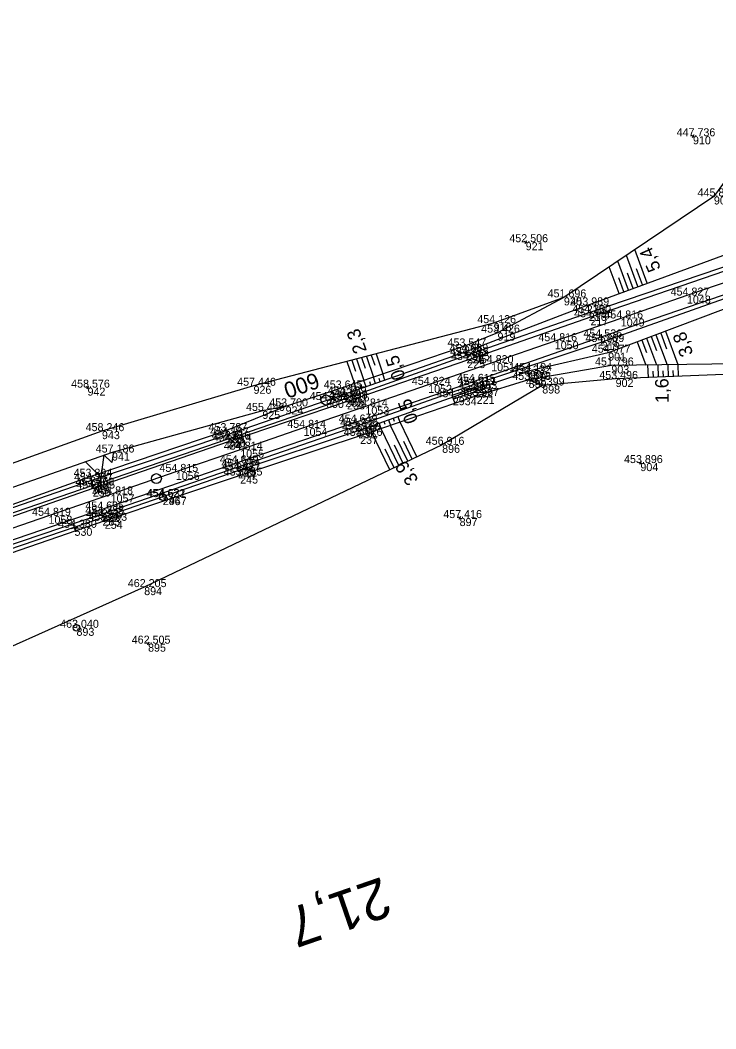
# Model space of a CAD drawing. Extents: x -751615 to -750797, y -1114905 to -1114561.
# Drawn here: x -751316.4 to -751212.2, y -1114822.9 to -1114671.7 of the extents above; entities that cross this region are included whole.
import ezdxf

# ---------------------------------------------------------------- set-up
doc = ezdxf.new("R2010")
doc.units = 0
for name, color, linetype in [('Vrstva 1', 7, 'Continuous'), ('Vrstva 4', 7, 'Continuous'), ('Vrstva 48', 7, 'Continuous'), ('Vrstva 49', 7, 'Continuous'), ('Vrstva 50', 7, 'Continuous'), ('Vrstva 53', 7, 'Continuous'), ('Vrstva 60', 7, 'Continuous'), ('Vrstva 61', 7, 'Continuous'), ('Vrstva 63', 7, 'Continuous'), ('Vrstva 7', 7, 'Continuous'), ('Vrstva 9', 7, 'Continuous')]:
    doc.layers.add(name, color=color, linetype=linetype)

msp = doc.modelspace()

# ---------------------------------------------------------------- linework, layer by layer
at = {"layer": 'Vrstva 1'}
msp.add_lwpolyline([(-751207.29, -1114709.83), (-751216.51, -1114713.01), (-751226.43, -1114716.44), (-751236.32, -1114719.85), (-751245.85, -1114723.14), (-751255.29, -1114726.39), (-751264.7, -1114729.64), (-751273.96, -1114732.84), (-751283.46, -1114736.11), (-751293.11, -1114739.44), (-751302.88, -1114742.81), (-751312.19, -1114746.02), (-751321.76, -1114749.32), (-751331.3, -1114752.61), (-751340.65, -1114755.84), (-751350.4, -1114759.2), (-751359.69, -1114762.41), (-751368.21, -1114765.34), (-751379.18, -1114769.13), (-751388.44, -1114772.32), (-751397.94, -1114775.61), (-751407.38, -1114778.86), (-751416.74, -1114782.09), (-751426.63, -1114785.5)], dxfattribs=at)
at = {"layer": 'Vrstva 4'}
for points in [[(-751187.89, -1114700.58), (-751206.03, -1114707.04), (-751231.23, -1114715.6), (-751249.54, -1114721.97), (-751267.72, -1114728.47), (-751285.3, -1114734.54), (-751305.69, -1114741.51), (-751323.63, -1114747.67), (-751344.16, -1114754.78), (-751362.44, -1114761.12), (-751382.65, -1114768), (-751419.83, -1114780.91), (-751439.84, -1114787.75), (-751459.65, -1114794.56), (-751479.26, -1114801.4), (-751499.56, -1114808.3), (-751517.66, -1114814.61), (-751524.47, -1114817.14), (-751524.91, -1114817.65)], [(-751186.45, -1114705.27), (-751204.57, -1114711.26), (-751229.26, -1114719.97), (-751248.51, -1114726.39), (-751266.03, -1114732.59), (-751283.83, -1114738.73), (-751304.21, -1114745.77), (-751322.37, -1114751.9), (-751342.61, -1114758.9), (-751360.96, -1114765.17), (-751381.11, -1114772.12), (-751418.54, -1114785), (-751438.61, -1114791.91), (-751458.17, -1114798.66), (-751477.81, -1114805.42), (-751497.9, -1114812.48), (-751516.51, -1114818.69), (-751522.39, -1114820.61), (-751523.2, -1114820.52)], [(-751205.8, -1114707.6), (-751230.97, -1114716.26), (-751249.42, -1114722.68), (-751267.45, -1114728.87), (-751285.11, -1114734.87), (-751305.56, -1114741.94), (-751323.35, -1114748.14), (-751343.96, -1114755.23), (-751362.41, -1114761.58), (-751382.45, -1114768.54), (-751419.68, -1114781.41), (-751439.79, -1114788.3), (-751459.37, -1114795.06), (-751479.15, -1114801.88), (-751499.34, -1114808.87), (-751517.57, -1114815.16), (-751524.91, -1114817.65)], [(-751204.68, -1114710.75), (-751229.56, -1114719.28), (-751248.53, -1114725.94), (-751266.25, -1114732.04), (-751284.07, -1114738.15), (-751304.21, -1114745.08), (-751322.47, -1114751.34), (-751342.64, -1114758.27), (-751361.14, -1114764.64), (-751381.34, -1114771.71), (-751418.71, -1114784.62), (-751438.73, -1114791.47), (-751458.26, -1114798.22), (-751477.95, -1114805), (-751498.18, -1114811.91), (-751516.63, -1114818.24), (-751523.2, -1114820.52)]]:
    msp.add_lwpolyline(points, dxfattribs=at)
at = {"layer": 'Vrstva 48'}
for p, q in [((-751222.46, -1114711.15), (-751224.31, -1114706.12)), ((-751225.27, -1114712.18), (-751226.87, -1114707.84)), ((-751223.87, -1114711.67), (-751225.59, -1114706.98)), ((-751226.68, -1114712.7), (-751228.15, -1114708.7)), ((-751223.16, -1114711.41), (-751224.05, -1114708.98)), ((-751225.98, -1114712.44), (-751226.74, -1114710.36)), ((-751224.57, -1114711.93), (-751225.4, -1114709.67)), ((-751219.75, -1114718.35), (-751217.88, -1114723.35)), ((-751223.97, -1114719.94), (-751222.66, -1114723.42)), ((-751223.26, -1114719.67), (-751222.56, -1114721.54)), ((-751222.56, -1114719.41), (-751221.07, -1114723.39)), ((-751221.86, -1114719.15), (-751221.06, -1114721.26)), ((-751221.16, -1114718.88), (-751219.47, -1114723.37)), ((-751220.45, -1114718.62), (-751219.56, -1114720.99)), ((-751267.47, -1114722.87), (-751266.34, -1114726.2)), ((-751266.75, -1114722.68), (-751266.19, -1114724.32)), ((-751266.02, -1114722.49), (-751264.92, -1114725.72)), ((-751265.29, -1114722.31), (-751264.75, -1114723.89)), ((-751264.56, -1114722.12), (-751263.5, -1114725.24)), ((-751263.84, -1114721.93), (-751263.31, -1114723.46)), ((-751263.11, -1114721.74), (-751262.08, -1114724.76)), ((-751222.28, -1114725.31), (-751222.35, -1114723.41)), ((-751221.53, -1114725.28), (-751221.57, -1114724.34)), ((-751220.78, -1114725.25), (-751220.85, -1114723.39)), ((-751220.03, -1114725.22), (-751220.07, -1114724.3)), ((-751219.28, -1114725.19), (-751219.35, -1114723.37)), ((-751218.53, -1114725.16), (-751218.57, -1114724.26)), ((-751217.78, -1114725.13), (-751217.85, -1114723.35)), ((-751264.6, -1114726.67), (-751264.92, -1114725.72)), ((-751263.89, -1114726.42), (-751264.05, -1114725.95)), ((-751263.18, -1114726.18), (-751263.5, -1114725.24)), ((-751262.48, -1114725.93), (-751262.64, -1114725.46)), ((-751261.77, -1114725.68), (-751262.08, -1114724.76)), ((-751266.02, -1114727.16), (-751266.34, -1114726.2)), ((-751265.31, -1114726.92), (-751265.47, -1114726.44)), ((-751262.66, -1114732.13), (-751262.37, -1114732.97)), ((-751261.95, -1114731.88), (-751261.8, -1114732.3)), ((-751261.25, -1114731.63), (-751260.95, -1114732.48)), ((-751260.54, -1114731.38), (-751260.39, -1114731.81)), ((-751259.83, -1114731.13), (-751259.53, -1114731.99)), ((-751257, -1114737.19), (-751259.49, -1114731.98)), ((-751264.08, -1114732.63), (-751263.78, -1114733.45)), ((-751261.06, -1114739.13), (-751263.78, -1114733.45)), ((-751263.37, -1114732.38), (-751263.22, -1114732.79)), ((-751259.71, -1114738.49), (-751262.35, -1114732.96)), ((-751258.36, -1114737.84), (-751260.92, -1114732.47)), ((-751257.68, -1114737.52), (-751258.94, -1114734.87)), ((-751260.39, -1114738.81), (-751261.72, -1114736.01)), ((-751259.03, -1114738.16), (-751260.33, -1114735.44))]:
    msp.add_line(p, q, dxfattribs=at)
at = {"layer": 'Vrstva 49'}
for p, q in [((-751215.38, -1114689.24), (-751215.83, -1114689.02)), ((-751215.5, -1114688.91), (-751215.72, -1114689.36)), ((-751240.46, -1114705.12), (-751240.91, -1114704.9)), ((-751240.57, -1114704.78), (-751240.79, -1114705.23)), ((-751231.53, -1114714.48), (-751209.62, -1114706.44)), ((-751238.2, -1114726.49), (-751240.24, -1114725.65)), ((-751306.12, -1114726.92), (-751306.57, -1114726.7)), ((-751306.24, -1114726.59), (-751306.45, -1114727.04)), ((-751223.27, -1114738.23), (-751223.72, -1114738.01)), ((-751223.38, -1114737.89), (-751223.6, -1114738.34)), ((-751250.35, -1114746.47), (-751250.8, -1114746.25)), ((-751250.47, -1114746.14), (-751250.69, -1114746.58)), ((-751297.04, -1114765.3), (-751297.49, -1114765.08)), ((-751297.16, -1114764.96), (-751297.38, -1114765.41))]:
    msp.add_line(p, q, dxfattribs=at)
for points in [[(-751159.89, -1114710.39), (-751159.56, -1114697.89), (-751162.61, -1114687.69), (-751171.31, -1114676.44), (-751182.9, -1114671.72), (-751191.58, -1114672.91), (-751197.98, -1114678.05), (-751212.47, -1114698.15), (-751234.95, -1114713.28), (-751244.9, -1114718.57)], [(-751201.1, -1114711.81), (-751208.03, -1114713.96), (-751228.32, -1114721.57), (-751240.07, -1114724.3)], [(-751234.95, -1114713.28), (-751245.48, -1114717.14), (-751281.47, -1114726.53), (-751304.18, -1114733.33), (-751349.01, -1114749.46), (-751398.2, -1114766.87), (-751445.8, -1114779.91), (-751491.92, -1114801.09), (-751522.47, -1114813.15), (-751523.88, -1114811.23), (-751530.06, -1114804.52)], [(-751231.53, -1114714.48), (-751249.64, -1114721.46), (-751267.89, -1114727.82), (-751285.51, -1114733.95), (-751305.91, -1114740.8), (-751324, -1114747.03), (-751344.27, -1114754.11), (-751362.59, -1114760.52), (-751382.59, -1114767.44), (-751402.41, -1114774.04), (-751420.23, -1114780.2), (-751439.89, -1114787.15), (-751459.92, -1114794.04), (-751479.47, -1114800.49), (-751499.79, -1114807.5), (-751517.87, -1114814.1), (-751523.11, -1114815.97), (-751524.21, -1114815.64), (-751526.18, -1114811.44)], [(-751244.9, -1114718.57), (-751249.94, -1114720.63), (-751268.48, -1114726.93), (-751276.66, -1114729.62), (-751285.76, -1114733.33), (-751305.98, -1114740.17), (-751324.13, -1114746.66), (-751344.39, -1114753.73), (-751362.68, -1114760.23), (-751382.77, -1114766.9), (-751402.56, -1114773.56), (-751420.5, -1114779.46), (-751440.12, -1114786.64), (-751460.29, -1114793.37), (-751479.7, -1114799.99), (-751499.94, -1114807), (-751518.24, -1114813.43), (-751522.74, -1114814.82), (-751523.67, -1114814.11), (-751524.93, -1114811.32)], [(-751523.9, -1114821.95), (-751516.26, -1114819.37), (-751497.39, -1114813.06), (-751477.62, -1114806.13), (-751458.02, -1114799.12), (-751438.43, -1114792.47), (-751418.48, -1114785.51), (-751400.56, -1114779.53), (-751380.1, -1114772.49), (-751360.67, -1114765.9), (-751342.47, -1114759.51), (-751322.29, -1114752.46), (-751304.11, -1114746.3), (-751283.78, -1114739.21), (-751265.74, -1114733.22), (-751248.29, -1114727.04), (-751240.07, -1114724.3)], [(-751204.75, -1114724.61), (-751227.2, -1114725.51), (-751238.2, -1114726.49), (-751253.2, -1114735.38), (-751297.85, -1114756.71), (-751332.9, -1114772.39), (-751375.5, -1114786.51), (-751400.7, -1114793.56), (-751443.21, -1114803.36), (-751482.54, -1114812.28)], [(-751205.22, -1114723.18), (-751227.84, -1114723.49), (-751240.24, -1114725.65)], [(-751240.24, -1114725.65), (-751248.02, -1114728.05), (-751265.49, -1114734.04), (-751283.47, -1114739.99), (-751303.76, -1114746.77), (-751322.17, -1114753.1), (-751342.49, -1114760), (-751360.52, -1114766.36), (-751379.96, -1114773.04), (-751400.34, -1114780.09), (-751418.29, -1114786.26), (-751438.17, -1114793.17), (-751457.68, -1114799.96), (-751477.22, -1114807.06), (-751497.38, -1114813.97), (-751516.22, -1114820.45), (-751522.92, -1114822.93), (-751523.9, -1114821.95)], [(-751276.66, -1114729.62), (-751280.14, -1114730.3), (-751302.67, -1114736.54), (-751347.76, -1114752.37), (-751397.37, -1114769.54), (-751443.61, -1114786.7), (-751459.32, -1114792.11), (-751460.29, -1114793.37)]]:
    msp.add_lwpolyline(points, dxfattribs=at)
at = {"layer": 'Vrstva 50'}
msp.add_lwpolyline([(-751302.47, -1114736.39), (-751302.69, -1114738.05), (-751303.89, -1114736.88), (-751304.33, -1114740.21), (-751306.72, -1114737.86)], dxfattribs=at)
at = {"layer": 'Vrstva 53'}
msp.add_line((-751307.96, -1114762.79), (-751308.05, -1114762.82), dxfattribs=at)
msp.add_circle((-751308, -1114762.81), 0.499, dxfattribs=at)
at = {"layer": 'Vrstva 60'}
for p, q in [((-751215.61, -1114689.13), (-751215.61, -1114689.13)), ((-751212.47, -1114698.15), (-751212.47, -1114698.15)), ((-751240.68, -1114705.01), (-751240.68, -1114705.01)), ((-751234.95, -1114713.28), (-751234.95, -1114713.28)), ((-751216.51, -1114713.01), (-751216.51, -1114713.01)), ((-751231.53, -1114714.48), (-751231.53, -1114714.48)), ((-751231.23, -1114715.6), (-751231.23, -1114715.6)), ((-751230.97, -1114716.26), (-751230.97, -1114716.26)), ((-751226.43, -1114716.44), (-751226.43, -1114716.44)), ((-751245.48, -1114717.14), (-751245.48, -1114717.14)), ((-751244.9, -1114718.57), (-751244.9, -1114718.57)), ((-751236.32, -1114719.85), (-751236.32, -1114719.85)), ((-751229.56, -1114719.28), (-751229.56, -1114719.28)), ((-751229.26, -1114719.97), (-751229.26, -1114719.97)), ((-751249.94, -1114720.63), (-751249.94, -1114720.63)), ((-751249.64, -1114721.46), (-751249.64, -1114721.46)), ((-751228.32, -1114721.57), (-751228.32, -1114721.57)), ((-751249.54, -1114721.97), (-751249.54, -1114721.97)), ((-751249.42, -1114722.68), (-751249.42, -1114722.68)), ((-751245.85, -1114723.14), (-751245.85, -1114723.14)), ((-751240.07, -1114724.3), (-751240.07, -1114724.3)), ((-751227.84, -1114723.49), (-751227.84, -1114723.49)), ((-751248.53, -1114725.94), (-751248.53, -1114725.94)), ((-751240.28, -1114724.69), (-751240.28, -1114724.69)), ((-751240.24, -1114725.65), (-751240.24, -1114725.65)), ((-751227.2, -1114725.51), (-751227.2, -1114725.51)), ((-751306.34, -1114726.81), (-751306.34, -1114726.81)), ((-751281.47, -1114726.53), (-751281.47, -1114726.53)), ((-751268.48, -1114726.93), (-751268.48, -1114726.93)), ((-751255.29, -1114726.39), (-751255.29, -1114726.39)), ((-751248.51, -1114726.39), (-751248.51, -1114726.39)), ((-751248.29, -1114727.04), (-751248.29, -1114727.04)), ((-751238.2, -1114726.49), (-751238.2, -1114726.49)), ((-751270.6, -1114728.66), (-751270.6, -1114728.66)), ((-751267.89, -1114727.82), (-751267.89, -1114727.82)), ((-751267.72, -1114728.47), (-751267.72, -1114728.47)), ((-751267.45, -1114728.87), (-751267.45, -1114728.87)), ((-751251.6, -1114728.25), (-751251.6, -1114728.25)), ((-751248.02, -1114728.05), (-751248.02, -1114728.05)), ((-751280.14, -1114730.3), (-751280.14, -1114730.3)), ((-751276.66, -1114729.62), (-751276.66, -1114729.62)), ((-751264.7, -1114729.64), (-751264.7, -1114729.64)), ((-751266.25, -1114732.04), (-751266.25, -1114732.04)), ((-751304.18, -1114733.33), (-751304.18, -1114733.33)), ((-751285.76, -1114733.33), (-751285.76, -1114733.33)), ((-751273.96, -1114732.84), (-751273.96, -1114732.84)), ((-751266.03, -1114732.59), (-751266.03, -1114732.59)), ((-751265.74, -1114733.22), (-751265.74, -1114733.22)), ((-751285.51, -1114733.95), (-751285.51, -1114733.95)), ((-751285.3, -1114734.54), (-751285.3, -1114734.54)), ((-751285.11, -1114734.87), (-751285.11, -1114734.87)), ((-751265.49, -1114734.04), (-751265.49, -1114734.04)), ((-751302.67, -1114736.54), (-751302.67, -1114736.54)), ((-751283.46, -1114736.11), (-751283.46, -1114736.11)), ((-751253.2, -1114735.38), (-751253.2, -1114735.38)), ((-751284.07, -1114738.15), (-751284.07, -1114738.15)), ((-751223.49, -1114738.12), (-751223.49, -1114738.12)), ((-751293.11, -1114739.44), (-751293.11, -1114739.44)), ((-751283.83, -1114738.73), (-751283.83, -1114738.73)), ((-751283.78, -1114739.21), (-751283.78, -1114739.21)), ((-751305.98, -1114740.17), (-751305.98, -1114740.17)), ((-751305.91, -1114740.8), (-751305.91, -1114740.8)), ((-751283.47, -1114739.99), (-751283.47, -1114739.99)), ((-751305.69, -1114741.51), (-751305.69, -1114741.51)), ((-751305.56, -1114741.94), (-751305.56, -1114741.94)), ((-751302.88, -1114742.81), (-751302.88, -1114742.81)), ((-751295.08, -1114743.22), (-751295.08, -1114743.22)), ((-751295.05, -1114743.21), (-751295.05, -1114743.21)), ((-751304.21, -1114745.08), (-751304.21, -1114745.08)), ((-751304.21, -1114745.77), (-751304.21, -1114745.77)), ((-751312.19, -1114746.02), (-751312.19, -1114746.02)), ((-751304.11, -1114746.3), (-751304.11, -1114746.3)), ((-751303.76, -1114746.77), (-751303.76, -1114746.77)), ((-751250.58, -1114746.36), (-751250.58, -1114746.36)), ((-751308.3, -1114747.82), (-751308.3, -1114747.82)), ((-751297.85, -1114756.71), (-751297.85, -1114756.71)), ((-751308, -1114762.81), (-751308, -1114762.81)), ((-751297.27, -1114765.19), (-751297.27, -1114765.19))]:
    msp.add_line(p, q, dxfattribs=at)
at = {"layer": 'Vrstva 63'}
msp.add_line((-751270.55, -1114728.64), (-751270.65, -1114728.68), dxfattribs=at)
msp.add_circle((-751270.6, -1114728.66), 0.756, dxfattribs=at)
at = {"layer": 'Vrstva 7'}
for p, q in [((-751239.81, -1114724.52), (-751240.76, -1114724.85)), ((-751240.12, -1114725.16), (-751240.45, -1114724.22)), ((-751295.03, -1114743.21), (-751295.12, -1114743.24)), ((-751295.01, -1114743.19), (-751295.1, -1114743.22)), ((-751307.83, -1114747.65), (-751308.77, -1114747.98)), ((-751308.14, -1114748.29), (-751308.46, -1114747.34))]:
    msp.add_line(p, q, dxfattribs=at)
for centre, radius in [((-751296.03, -1114740.45), 0.75), ((-751295.08, -1114743.22), 0.5), ((-751295.05, -1114743.21), 0.5)]:
    msp.add_circle(centre, radius, dxfattribs=at)
at = {"layer": 'Vrstva 9'}
msp.add_lwpolyline([(-751251.32, -1114729.1), (-751251.51, -1114728.53), (-751251.7, -1114727.96), (-751246.96, -1114726.36), (-751246.77, -1114726.93), (-751251.51, -1114728.53)], dxfattribs=at)

# ---------------------------------------------------------------- texts
at = {"layer": 'Vrstva 48'}
for s, rotation, p in [('5,4', 113.9405, (-751220.38, -1114708.93)), ('2,3', 109.6266, (-751264.45, -1114721.29)), ('3,8', 110.5644, (-751215.54, -1114721.72)), ('0,5', 108.768, (-751258.67, -1114725.29)), ('1,6', 90.77, (-751219.24, -1114729.12)), ('0,5', 109.5075, (-751256.77, -1114731.79)), ('3,9', 123.9304, (-751256.67, -1114740.61))]:
    msp.add_text(s, height=2, rotation=rotation, dxfattribs=at).set_placement(p)
at = {"layer": 'Vrstva 60'}
for s, p in [('910', (-751215.61, -1114690.33)), ('909', (-751212.47, -1114699.35)), ('921', (-751240.68, -1114706.21)), ('920', (-751234.95, -1114714.48)), ('1048', (-751216.51, -1114714.21)), ('215', (-751231.53, -1114715.68)), ('216', (-751231.23, -1114716.8)), ('217', (-751230.97, -1114717.46)), ('1049', (-751226.43, -1114717.64)), ('918', (-751245.48, -1114718.33)), ('919', (-751244.9, -1114719.77)), ('1050', (-751236.32, -1114721.05)), ('218', (-751229.56, -1114720.48)), ('219', (-751229.26, -1114721.17)), ('228', (-751249.94, -1114721.83)), ('227', (-751249.64, -1114722.66)), ('901', (-751228.32, -1114722.77)), ('226', (-751249.54, -1114723.17)), ('225', (-751249.42, -1114723.88)), ('1051', (-751245.85, -1114724.34)), ('900', (-751240.07, -1114725.5)), ('903', (-751227.84, -1114724.69)), ('224', (-751248.53, -1114727.14)), ('529', (-751240.28, -1114725.89)), ('899', (-751240.24, -1114726.85)), ('902', (-751227.2, -1114726.71)), ('942', (-751306.34, -1114728.01)), ('926', (-751281.47, -1114727.73)), ('230', (-751268.48, -1114728.13)), ('1052', (-751255.29, -1114727.59)), ('223', (-751248.51, -1114727.59)), ('222', (-751248.29, -1114728.24)), ('898', (-751238.2, -1114727.69)), ('600', (-751270.6, -1114729.86)), ('231', (-751267.89, -1114729.02)), ('232', (-751267.72, -1114729.67)), ('233', (-751267.45, -1114730.07)), ('2934', (-751251.6, -1114729.45)), ('221', (-751248.02, -1114729.25)), ('925', (-751280.14, -1114731.5)), ('924', (-751276.66, -1114730.82)), ('1053', (-751264.7, -1114730.84)), ('234', (-751266.25, -1114733.24)), ('943', (-751304.18, -1114734.53)), ('238', (-751285.76, -1114734.53)), ('1054', (-751273.96, -1114734.04)), ('235', (-751266.03, -1114733.79)), ('236', (-751265.74, -1114734.42)), ('239', (-751285.51, -1114735.15)), ('240', (-751285.3, -1114735.74)), ('241', (-751285.11, -1114736.07)), ('237', (-751265.49, -1114735.24)), ('941', (-751302.67, -1114737.74)), ('1055', (-751283.46, -1114737.31)), ('896', (-751253.2, -1114736.58)), ('242', (-751284.07, -1114739.35)), ('904', (-751223.49, -1114739.32)), ('1056', (-751293.11, -1114740.64)), ('243', (-751283.83, -1114739.93)), ('244', (-751283.78, -1114740.41)), ('247', (-751305.98, -1114741.36)), ('248', (-751305.91, -1114742)), ('245', (-751283.47, -1114741.19)), ('249', (-751305.69, -1114742.71)), ('250', (-751305.56, -1114743.14)), ('1057', (-751302.88, -1114744.01)), ('246', (-751295.08, -1114744.42)), ('2947', (-751295.05, -1114744.41)), ('251', (-751304.21, -1114746.28)), ('252', (-751304.21, -1114746.97)), ('1058', (-751312.19, -1114747.22)), ('253', (-751304.11, -1114747.5)), ('254', (-751303.76, -1114747.97)), ('897', (-751250.58, -1114747.56)), ('530', (-751308.3, -1114749.02)), ('894', (-751297.85, -1114757.91)), ('893', (-751308, -1114764.01)), ('895', (-751297.27, -1114766.39))]:
    msp.add_text(s, height=1.2, dxfattribs=at).set_placement(p)
at = {"layer": 'Vrstva 61'}
for s, p in [('447.736', (-751218.06, -1114689.13)), ('445.836', (-751214.92, -1114698.15)), ('452.506', (-751243.13, -1114705.01)), ('451.696', (-751237.4, -1114713.28)), ('454.827', (-751218.96, -1114713.01)), ('453.989', (-751233.98, -1114714.48)), ('454.300', (-751233.69, -1114715.6)), ('454.596', (-751233.42, -1114716.26)), ('454.816', (-751228.89, -1114716.44)), ('454.126', (-751247.93, -1114717.14)), ('453.426', (-751247.35, -1114718.57)), ('454.536', (-751232.02, -1114719.28)), ('453.547', (-751252.39, -1114720.63)), ('454.816', (-751238.78, -1114719.85)), ('454.309', (-751231.71, -1114719.97)), ('454.089', (-751252.09, -1114721.46)), ('454.225', (-751252, -1114721.97)), ('454.595', (-751251.87, -1114722.68)), ('454.077', (-751230.77, -1114721.57)), ('454.820', (-751248.3, -1114723.14)), ('454.194', (-751242.52, -1114724.3)), ('451.796', (-751230.29, -1114723.49)), ('454.222', (-751242.73, -1114724.69)), ('453.573', (-751242.69, -1114725.65)), ('453.496', (-751229.65, -1114725.51)), ('458.576', (-751308.8, -1114726.81)), ('457.446', (-751283.92, -1114726.53)), ('453.645', (-751270.94, -1114726.93)), ('454.824', (-751257.74, -1114726.39)), ('454.615', (-751250.98, -1114725.94)), ('454.311', (-751250.87, -1114726.39)), ('454.153', (-751250.74, -1114727.04)), ('454.399', (-751240.65, -1114726.49)), ('454.132', (-751273.05, -1114728.66)), ('454.169', (-751270.34, -1114727.82)), ('454.298', (-751270.18, -1114728.47)), ('454.616', (-751269.9, -1114728.87)), ('454.392', (-751254.05, -1114728.25)), ('453.567', (-751250.47, -1114728.05)), ('455.446', (-751282.59, -1114730.3)), ('453.700', (-751279.11, -1114729.62)), ('454.814', (-751267.15, -1114729.64)), ('458.246', (-751306.63, -1114733.33)), ('453.787', (-751288.21, -1114733.33)), ('454.814', (-751276.41, -1114732.84)), ('454.649', (-751268.7, -1114732.04)), ('454.245', (-751268.49, -1114732.59)), ('454.168', (-751268.19, -1114733.22)), ('454.197', (-751287.97, -1114733.95)), ('454.316', (-751287.75, -1114734.54)), ('454.614', (-751287.56, -1114734.87)), ('453.676', (-751267.94, -1114734.04)), ('454.814', (-751285.91, -1114736.11)), ('456.916', (-751255.66, -1114735.38)), ('457.186', (-751305.12, -1114736.54)), ('454.815', (-751295.56, -1114739.44)), ('454.649', (-751286.52, -1114738.15)), ('454.274', (-751286.28, -1114738.73)), ('454.227', (-751286.23, -1114739.21)), ('453.896', (-751225.94, -1114738.12)), ('453.894', (-751308.43, -1114740.17)), ('454.247', (-751308.36, -1114740.8)), ('453.755', (-751285.93, -1114739.99)), ('454.360', (-751308.14, -1114741.51)), ('454.695', (-751308.02, -1114741.94)), ('454.818', (-751305.33, -1114742.81)), ('454.622', (-751297.5, -1114743.21)), ('454.631', (-751297.43, -1114743.22)), ('454.695', (-751306.67, -1114745.08)), ('454.819', (-751314.65, -1114746.02)), ('454.235', (-751306.67, -1114745.77)), ('454.237', (-751306.56, -1114746.3)), ('453.893', (-751306.21, -1114746.77)), ('457.416', (-751253.03, -1114746.36)), ('454.380', (-751310.75, -1114747.82)), ('462.205', (-751300.31, -1114756.71)), ('463.040', (-751310.45, -1114762.81)), ('462.505', (-751299.72, -1114765.19))]:
    msp.add_text(s, height=1.2, dxfattribs=at).set_placement(p)
at = {"layer": 'Vrstva 63'}
msp.add_text('600', height=2.4, rotation=199.0555, dxfattribs=at).set_placement((-751272.11, -1114724.48))
at = {"layer": 'Vrstva 7'}
msp.add_text('21,7', height=6, rotation=199.0204, dxfattribs=at).set_placement((-751262.23, -1114800.09))

doc.saveas('drawing.dxf')
